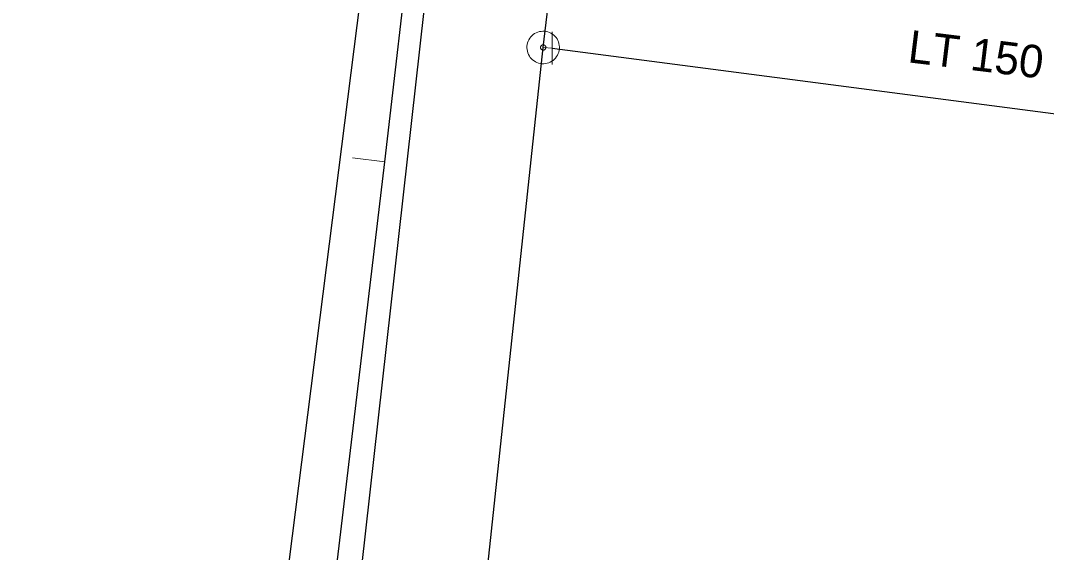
# Model space of a CAD drawing. Extents: x -783064 to -782702, y -1007904 to -1007145.
# Drawn here: x -782795.29 to -782763.75, y -1007436.69 to -1007420.35 of the extents above; entities that cross this region are included whole.
import ezdxf

# ---------------------------------------------------------------- set-up
doc = ezdxf.new("R2010")
doc.units = 0
doc.header["$LTSCALE"] = 0.4
for name, color, linetype, lineweight in [('1', 7, 'Continuous', 13), ('11', 7, 'Continuous', 13), ('14', 7, 'Continuous', 13), ('17', 7, 'Continuous', 25), ('34', 7, 'Continuous', 13), ('47', 7, 'Continuous', 13)]:
    doc.layers.add(name, color=color, linetype=linetype, lineweight=lineweight)

msp = doc.modelspace()

# ---------------------------------------------------------------- linework, layer by layer
at = {"layer": '11'}
msp.add_line((-782785.087, -1007424.571), (-782784.094, -1007424.689), dxfattribs=at)
at = {"layer": '14'}
msp.add_line((-782779.226, -1007421.176), (-782778.949, -1007421.2), dxfattribs=at)
at = {"layer": '14', "lineweight": 25}
for points in [[(-782789.989, -1007474.3), (-782789.55, -1007470.605), (-782788.26, -1007459.742), (-782786.499, -1007444.926), (-782784.094, -1007424.689), (-782783.243, -1007417.342), (-782782.853, -1007416.665)], [(-782789.92, -1007482.8), (-782782.627, -1007417.749), (-782782.853, -1007416.665)]]:
    msp.add_lwpolyline(points, dxfattribs=at)
at = {"layer": '17'}
msp.add_line((-782779.226, -1007421.176), (-782777.911, -1007410.054), dxfattribs=at)
for points in [[(-782784.199, -1007414.51), (-782788.17, -1007445.88), (-782789.899, -1007459.31), (-782791.09, -1007469.35), (-782793.219, -1007488.27), (-782794.285, -1007499.072), (-782794.78, -1007504.08), (-782795.89, -1007514.14), (-782797.23, -1007526.05), (-782799.52, -1007547.12), (-782801.219, -1007562.54)], [(-782794.527, -1007563.539), (-782793.17, -1007552.95), (-782792.78, -1007548.16), (-782791.739, -1007539.74), (-782790.94, -1007531.25), (-782789.17, -1007514.32), (-782788.309, -1007505.04), (-782787.02, -1007493.25), (-782786.27, -1007487.64), (-782784.98, -1007475.07), (-782783.55, -1007462.11), (-782782.149, -1007449.41), (-782782.032, -1007447.451), (-782779.226, -1007421.176)], [(-782778.949, -1007421.2), (-782751.447, -1007424.784), (-782747.808, -1007425.172)]]:
    msp.add_lwpolyline(points, dxfattribs=at)
at = {"layer": '34'}
msp.add_line((-782778.949, -1007420.7), (-782778.949, -1007421.7), dxfattribs=at)
at = {"layer": '47'}
for points in [[(-782778.775, -1007420.959), (-782778.8, -1007420.913), (-782778.83, -1007420.87), (-782778.864, -1007420.831), (-782778.901, -1007420.795), (-782778.943, -1007420.763), (-782778.989, -1007420.736), (-782779.036, -1007420.714), (-782779.085, -1007420.696), (-782779.135, -1007420.684), (-782779.188, -1007420.677), (-782779.24, -1007420.676), (-782779.292, -1007420.681), (-782779.343, -1007420.69), (-782779.394, -1007420.705), (-782779.442, -1007420.725), (-782779.488, -1007420.75), (-782779.531, -1007420.78), (-782779.571, -1007420.814), (-782779.606, -1007420.851), (-782779.638, -1007420.893), (-782779.665, -1007420.939), (-782779.688, -1007420.986), (-782779.705, -1007421.035), (-782779.718, -1007421.086), (-782779.724, -1007421.138), (-782779.725, -1007421.19), (-782779.721, -1007421.243), (-782779.711, -1007421.293), (-782779.696, -1007421.344), (-782779.676, -1007421.392), (-782779.651, -1007421.438), (-782779.621, -1007421.481), (-782779.587, -1007421.521), (-782779.55, -1007421.556), (-782779.508, -1007421.588), (-782779.463, -1007421.616), (-782779.416, -1007421.639), (-782779.366, -1007421.656), (-782779.315, -1007421.668), (-782779.263, -1007421.674), (-782779.211, -1007421.675), (-782779.159, -1007421.672), (-782779.108, -1007421.661), (-782779.057, -1007421.646), (-782779.009, -1007421.626), (-782778.963, -1007421.601), (-782778.92, -1007421.571), (-782778.881, -1007421.538), (-782778.845, -1007421.5), (-782778.813, -1007421.458), (-782778.785, -1007421.413), (-782778.763, -1007421.366), (-782778.746, -1007421.317), (-782778.734, -1007421.266), (-782778.727, -1007421.213), (-782778.726, -1007421.161), (-782778.73, -1007421.11), (-782778.74, -1007421.058), (-782778.755, -1007421.007)], [(-782779.152, -1007421.14), (-782779.155, -1007421.132), (-782779.161, -1007421.126), (-782779.166, -1007421.119), (-782779.172, -1007421.113), (-782779.179, -1007421.108), (-782779.187, -1007421.104), (-782779.194, -1007421.1), (-782779.202, -1007421.097), (-782779.211, -1007421.095), (-782779.219, -1007421.094), (-782779.228, -1007421.094), (-782779.237, -1007421.094), (-782779.245, -1007421.096), (-782779.253, -1007421.098), (-782779.261, -1007421.102), (-782779.269, -1007421.105), (-782779.275, -1007421.111), (-782779.282, -1007421.116), (-782779.288, -1007421.122), (-782779.293, -1007421.129), (-782779.297, -1007421.137), (-782779.301, -1007421.144), (-782779.304, -1007421.152), (-782779.307, -1007421.161), (-782779.307, -1007421.169), (-782779.307, -1007421.178), (-782779.307, -1007421.187), (-782779.305, -1007421.195), (-782779.303, -1007421.203), (-782779.299, -1007421.211), (-782779.296, -1007421.219), (-782779.29, -1007421.225), (-782779.285, -1007421.232), (-782779.279, -1007421.238), (-782779.272, -1007421.243), (-782779.265, -1007421.248), (-782779.257, -1007421.251), (-782779.249, -1007421.254), (-782779.24, -1007421.257), (-782779.232, -1007421.257), (-782779.223, -1007421.257), (-782779.214, -1007421.257), (-782779.206, -1007421.255), (-782779.198, -1007421.253), (-782779.19, -1007421.249), (-782779.182, -1007421.246), (-782779.176, -1007421.24), (-782779.169, -1007421.235), (-782779.163, -1007421.229), (-782779.158, -1007421.222), (-782779.153, -1007421.215), (-782779.15, -1007421.207), (-782779.147, -1007421.199), (-782779.145, -1007421.19), (-782779.144, -1007421.182), (-782779.144, -1007421.173), (-782779.144, -1007421.164), (-782779.146, -1007421.156), (-782779.148, -1007421.148)]]:
    msp.add_lwpolyline(points, close=True, dxfattribs=at)

# ---------------------------------------------------------------- texts
at = {"layer": '1'}
msp.add_text('LT 150', height=1, rotation=353, dxfattribs=at).set_placement((-782768.046, -1007421.627))

doc.saveas('drawing.dxf')
